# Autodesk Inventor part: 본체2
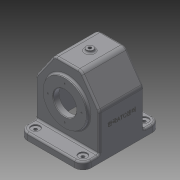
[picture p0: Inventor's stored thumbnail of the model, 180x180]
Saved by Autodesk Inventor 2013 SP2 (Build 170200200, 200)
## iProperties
Created: 2022-12
Part Number: 본체2
Material: Generic
Document SubType Name: Modeling
Designer: i
Density: 1 g/cm^3
Author: i
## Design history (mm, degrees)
sketch "스케치1"
  geometry: L1 (38.5, 55)-(-38.5, 55); L2 (-38.5, 55)-(-38.5, -55); L3 (-38.5, -55)-(38.5, -55); L4 (38.5, -55)-(38.5, 55); L5 (38.5, 55)-(-38.5, -55); L6 (-38.5, 55)-(38.5, -55); L7 (38.5, 55)-(83.5, 23.491); L8 (38.5, 55)-(93.435, 55); L9 (83.5, 23.491)-(83.5, -23.491); L10 (83.5, -23.491)-(38.5, -55); 1 further point
  constraints: 20 end point, 2 horizontal, 2 midpoint, 2 parallel, 2 perpendicular, 1 equal length
  dimensions: "d0" = 77 distance of L3.end L2.end; "d1" = 110 distance of L2.end L1.end; "d2" = 35 deg angle of L7 L8; "d4" = 125 deg angle of L9 L10; "d5" = 122 distance between parallel lines of L9 L2
extrude "돌출1" new body sketch "스케치1" stored distance "d6" = 77; taper "d7" = 0 deg
sketch "스케치2"
  geometry: L1 (-55, -38.5)-(55, -38.5) reference; C1 r 31 at (0, 26.5); 1 further point
  constraints: 1 centre point
  dimensions: "d8" = 62 diameter of C1; "d10" = 65 distance from line of C1.centre L1
extrude "돌출2" join sketch "스케치2" distance "d11" = 10; taper "d12" = 0 deg
sketch "스케치3"
  geometry: C1 r 31 at (0, 0) reference; C2 r 20 at (0, 0); 1 further point
  constraints: 1 centre point, 1 coincident
  dimensions: "d13" = 40 diameter of C2
extrude "돌출3" cut sketch "스케치3" stored distance "d14" = 15; taper "d15" = 0 deg
sketch "스케치4"
  geometry: L1 (-55, -38.5)-(55, -38.5) reference; C1 r 37.5 at (0, 26.5); 1 further point
  constraints: 1 centre point
  dimensions: "d16" = 75 diameter of C1; "d17" = 65 distance from line of L1 C1.centre
extrude "돌출4" join sketch "스케치4" distance "d18" = 5; taper "d19" = 0 deg
sketch "스케치5"
  geometry: C1 r 37.5 at (0, 0) reference; C2 r 20 at (0, 0); 1 further point
  constraints: 1 centre point, 1 coincident
  dimensions: "d20" = 40 diameter of C2
extrude "돌출6" cut sketch "스케치5" distance "d23" = 24; taper "d24" = 0 deg
sketch "스케치6"
  geometry: L1 (0, 0)-(0, 26); C1 r 31 at (0, 0) reference; 2 further points
  constraints: 2 end point, 1 coincident, 1 vertical
  dimensions: "d25" = 26 distance of L1.start L1.end
hole "구멍1" sketch "스케치6" at (0, 26) diameter "d26" = 2.459; stored, may be unused: countersink angle "d30" = 90 deg, drill point angle "d32" = 118 deg; dims "d27" = 6, "d28" = 4, "d29" = 2, "d31" = 8
sketch "스케치7"
  geometry: L1 (0, 0)-(0, 29); C1 r 37.5 at (0, 0) reference; 2 further points
  constraints: 2 end point, 1 coincident, 1 vertical
  dimensions: "d36" = 29 distance of L1.start L1.end
hole "구멍2" sketch "스케치7" at (0, 29) diameter "d37" = 2.459; stored, may be unused: countersink angle "d41" = 90 deg, drill point angle "d43" = 118 deg; dims "d38" = 6, "d39" = 4, "d40" = 2, "d42" = 8
sketch "스케치8"
  geometry: L1 (0, 0)-(77, 0) reference; L2 (77, 110)-(77, 0) reference; L3 (0, 110)-(77, 110) reference; L4 (0, 0)-(0, 110) reference; L5 (-28.5, 110)-(105.5, 110); L6 (105.5, 110)-(105.5, 0); L7 (105.5, 0)-(-28.5, 0); L8 (-28.5, 0)-(-28.5, 110); L9 (-28.5, 110)-(105.5, 0); L10 (105.5, 110)-(-28.5, 0); 1 further point
  constraints: 12 end point, 2 midpoint, 2 parallel, 1 horizontal, 1 perpendicular
  dimensions: "d47" = 134 distance of L6.end L7.end; "d48" = 110 distance of L5.end L6.end
extrude "돌출7" join sketch "스케치8" distance "d49" = 12; taper "d50" = 0 deg
fillet "모깎기1" dims "d51" = 14
sketch "스케치9"
  geometry: L1 (91.5, 0)-(77, 0) reference; L2 (77, -110)-(77, 0) reference; L3 (77, -110)-(91.5, -110) reference; L4 (105.5, -96)-(105.5, -14) reference; A1 r 14 centre (-14.5, -14) between (-14.5, 0) and (-28.5, -14) reference; A2 r 14 centre (-14.5, -96) between (-28.5, -96) and (-14.5, -110) reference; A3 r 14 centre (91.5, -14) between (105.5, -14) and (91.5, 0) reference; A4 r 14 centre (91.5, -96) between (91.5, -110) and (105.5, -96) reference; 5 further points
  constraints: 4 coincident
hole "구멍3" sketch "스케치9" at (-14.5, -14), (91.5, -14), (91.5, -96), (-14.5, -96) diameter "d52" = 5.5; stored, may be unused: countersink angle "d56" = 90 deg, drill point angle "d58" = 118 deg; dims "d53" = 6, "d54" = 15, "d55" = 2, "d57" = 8
sketch "스케치12"
  geometry: C1 r 6 at (38.5, 23.491); 1 further point
  constraints: 1 centre point, 1 coincident
  dimensions: "d69" = 12 diameter of C1
extrude "돌출10" join sketch "스케치12" distance "d70" = 4; taper "d71" = 0 deg
sketch "스케치13"
  geometry: C1 r 6 at (0, 0) reference; 1 further point
  constraints: 1 coincident
hole "구멍4" sketch "스케치13" at (0, 0) diameter "d72" = 5.188; stored, may be unused: countersink angle "d76" = 90 deg, drill point angle "d78" = 118 deg; dims "d73" = 12, "d74" = 15, "d75" = 2, "d77" = 8
feature "쉘3" dims "d99" = 5
fillet "모깎기2" dims "d84" = 10
chamfer "모따기1" distance "d86" = 1; stored, may be unused: second distance "d87" = 2, angle "d88" = 45 deg
fillet "모깎기4" dims "d89" = 3
fillet "모깎기3" dims "d85" = 3
sketch "스케치15"
  geometry: L1 (0, 0)-(106, 0) reference; L2 (14.5, 73.847)-(14.5, 15) reference; L3 (-14, 9)-(-14, 0) reference; 2 further points
  constraints: 1 other
  dimensions: "d90" = 50 distance from line of L1 point (53, 50); "d91" = 38.5 distance from line of point (53, 50) L2; "d94" = 28.5 distance between parallel lines of L2 L3 (derived)
feature "엠보싱1" sketch "스케치15" dims "d0" = 77, "d1" = 110, "d2" = 35 deg, "d4" = 125 deg, "d5" = 122, "d13" = 40, "d92" = 0.5, "d93" = 0
sketch "스케치14"
  geometry: L1 (-100.5, 91)-(-33.5, 91); L2 (-33.5, 91)-(-33.5, -9); L3 (-33.5, -9)-(-100.5, -9); L4 (-100.5, -9)-(-100.5, 91); L5 (-100.5, 91)-(-33.5, -9); L6 (-33.5, 91)-(-100.5, -9); C1 r 2.594 at (-67, 41) reference
  constraints: 12 end point, 2 midpoint, 2 parallel, 1 horizontal, 1 perpendicular
  dimensions: "d80" = 67 distance of L2.end L3.end; "d81" = 100 distance of L1.end L2.end
extrude "돌출11" cut sketch "스케치14" distance "d82" = 77; taper "d83" = 0 deg
node "솔리드1"
pattern_circular "원형 패턴1" dims angle "d34" = 360 deg
pattern_circular "원형 패턴2" dims angle "d45" = 360 deg
node "투영된 루프1"
